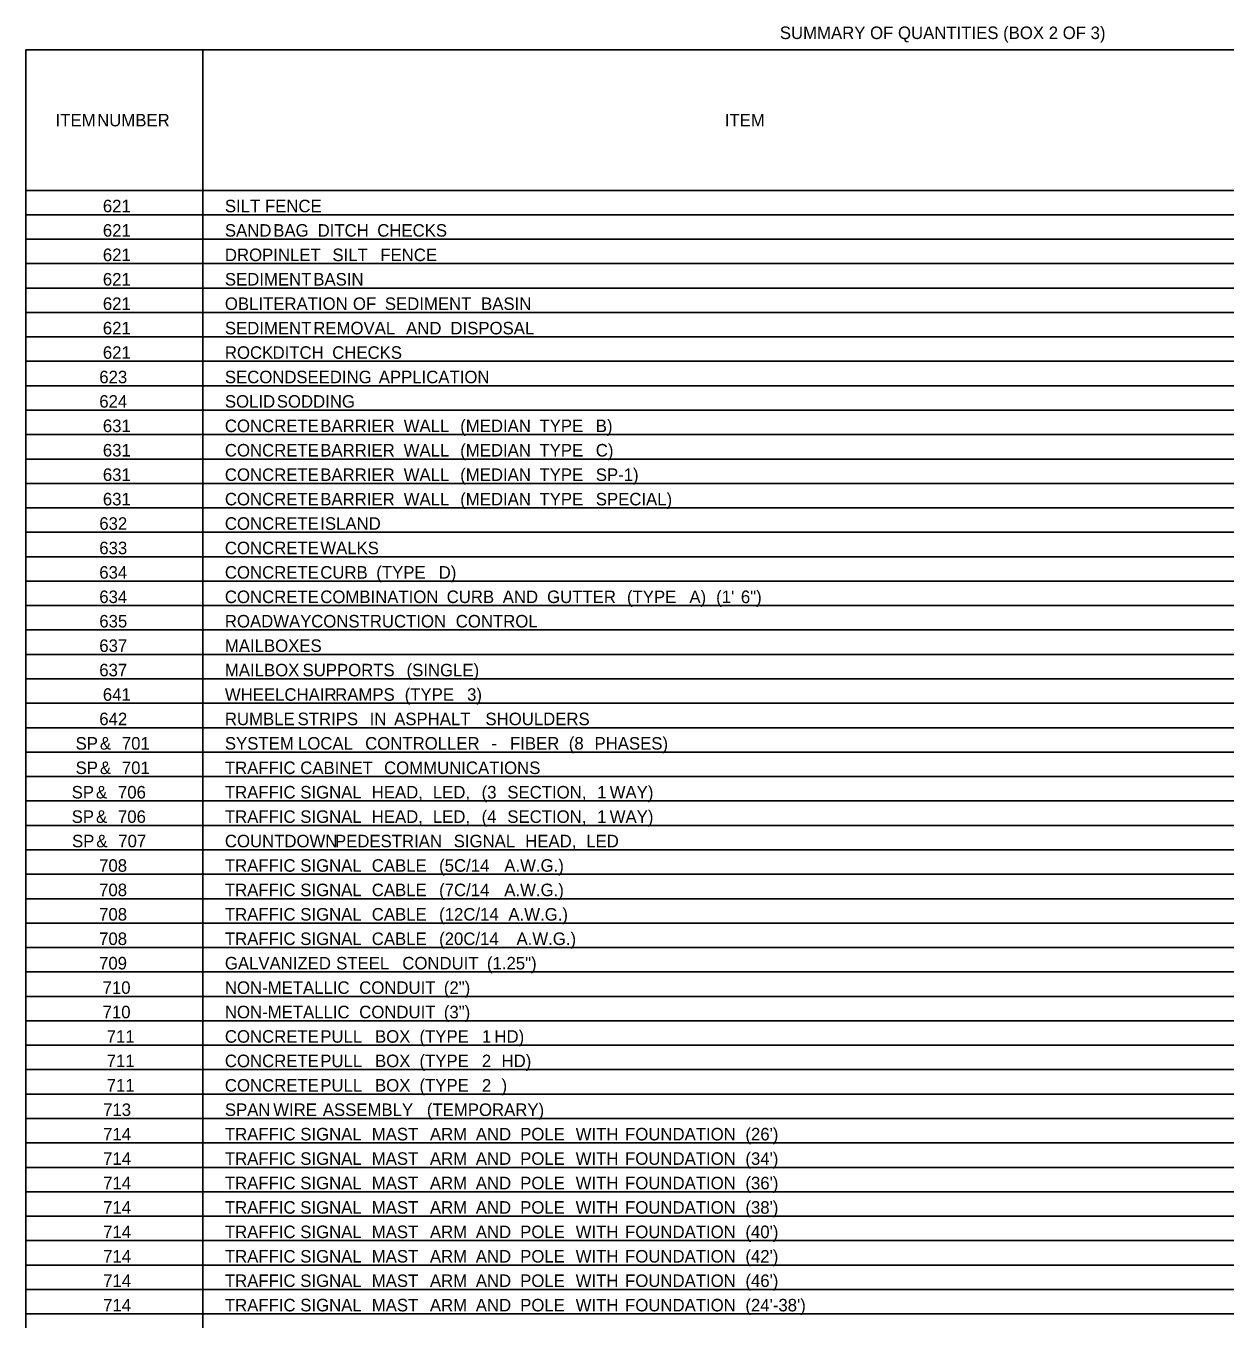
# Model space of a CAD drawing. Extents: x 1226603 to 1228117, y 151305 to 152343.
# Drawn here: x 1227295.3 to 1227702.3, y 151801.3 to 152240.1 of the extents above; entities that cross this region are included whole.
import ezdxf

# ---------------------------------------------------------------- set-up
doc = ezdxf.new("R2010")
doc.units = 0
doc.layers.add('R_Dimension', color=7, linetype='Continuous')

msp = doc.modelspace()

# ---------------------------------------------------------------- linework, layer by layer
at = {"layer": 'R_Dimension'}
for p, q in [((1227295.33, 152231.95), (1227925.18, 152231.95)), ((1227295.33, 151330.69), (1227295.33, 152231.95)), ((1227355.42, 151330.69), (1227355.42, 152231.95)), ((1227295.33, 152184.3), (1227925.18, 152184.3)), ((1227295.33, 152176.01), (1227925.18, 152176.01)), ((1227295.33, 152167.73), (1227925.18, 152167.73)), ((1227295.33, 152159.44), (1227925.18, 152159.44)), ((1227295.33, 152151.15), (1227925.18, 152151.15)), ((1227295.33, 152142.86), (1227925.18, 152142.86)), ((1227295.33, 152134.58), (1227925.18, 152134.58)), ((1227295.33, 152126.29), (1227925.18, 152126.29)), ((1227295.33, 152118), (1227925.18, 152118)), ((1227295.33, 152109.71), (1227925.18, 152109.71)), ((1227295.33, 152101.43), (1227925.18, 152101.43)), ((1227295.33, 152093.14), (1227925.18, 152093.14)), ((1227295.33, 152084.85), (1227925.18, 152084.85)), ((1227295.33, 152076.56), (1227925.18, 152076.56)), ((1227295.33, 152068.28), (1227925.18, 152068.28)), ((1227295.33, 152059.99), (1227925.18, 152059.99)), ((1227295.33, 152051.7), (1227925.18, 152051.7)), ((1227295.33, 152043.41), (1227925.18, 152043.41)), ((1227295.33, 152035.13), (1227925.18, 152035.13)), ((1227295.33, 152026.84), (1227925.18, 152026.84)), ((1227295.33, 152018.55), (1227925.18, 152018.55)), ((1227295.33, 152010.26), (1227925.18, 152010.26)), ((1227295.33, 152001.98), (1227925.18, 152001.98)), ((1227295.33, 151993.69), (1227925.18, 151993.69)), ((1227295.33, 151985.4), (1227925.18, 151985.4)), ((1227295.33, 151977.11), (1227925.18, 151977.11)), ((1227295.33, 151968.83), (1227925.18, 151968.83)), ((1227295.33, 151960.54), (1227925.18, 151960.54)), ((1227295.33, 151952.25), (1227925.18, 151952.25)), ((1227295.33, 151943.96), (1227925.18, 151943.96)), ((1227295.33, 151935.68), (1227925.18, 151935.68)), ((1227295.33, 151927.39), (1227925.18, 151927.39)), ((1227295.33, 151919.1), (1227925.18, 151919.1)), ((1227295.33, 151910.81), (1227925.18, 151910.81)), ((1227295.33, 151902.53), (1227925.18, 151902.53)), ((1227295.33, 151894.24), (1227925.18, 151894.24)), ((1227295.33, 151885.95), (1227925.18, 151885.95)), ((1227295.33, 151877.66), (1227925.18, 151877.66)), ((1227295.33, 151869.38), (1227925.18, 151869.38)), ((1227295.33, 151861.09), (1227925.18, 151861.09)), ((1227295.33, 151852.8), (1227925.18, 151852.8)), ((1227295.33, 151844.51), (1227925.18, 151844.51)), ((1227295.33, 151836.23), (1227925.18, 151836.23)), ((1227295.33, 151827.94), (1227925.18, 151827.94)), ((1227295.33, 151819.65), (1227925.18, 151819.65)), ((1227295.33, 151811.36), (1227925.18, 151811.36)), ((1227295.33, 151803.08), (1227925.18, 151803.08))]:
    msp.add_line(p, q, dxfattribs=at)

# ---------------------------------------------------------------- texts
for s, p in [('SUMMARY OF QUANTITIES (BOX 2 OF 3)', (1227551.19, 152235.63)), ('ITEM', (1227305.43, 152206)), (' NUMBER', (1227317.94, 152206)), ('ITEM', (1227532.52, 152206)), ('621', (1227321.46, 152176.86)), ('SILT', (1227362.87, 152176.86)), (' FENCE', (1227374.89, 152176.86)), ('621', (1227321.46, 152168.58)), ('SAND', (1227362.87, 152168.58)), (' BAG', (1227377.7, 152168.58)), (' DITCH', (1227392.76, 152168.58)), (' CHECKS', (1227413, 152168.58)), ('621', (1227321.46, 152160.29)), ('DROP', (1227362.87, 152160.29)), (' INLET', (1227377.7, 152160.29)), (' SILT', (1227397.78, 152160.29)), (' FENCE', (1227414.04, 152160.29)), ('621', (1227321.46, 152152)), ('SEDIMENT', (1227362.87, 152152)), (' BASIN', (1227391.29, 152152)), ('621', (1227321.46, 152143.71)), ('OBLITERATION', (1227362.87, 152143.71)), (' OF', (1227404.74, 152143.71)), (' SEDIMENT', (1227415.58, 152143.71)), (' BASIN', (1227448.24, 152143.71)), ('621', (1227321.46, 152135.43)), ('SEDIMENT', (1227362.87, 152135.43)), (' REMOVAL', (1227391.29, 152135.43)), (' AND', (1227422.78, 152135.43)), (' DISPOSAL', (1227437.84, 152135.43)), ('621', (1227321.46, 152127.14)), ('ROCK', (1227362.87, 152127.14)), (' DITCH', (1227377.47, 152127.14)), (' CHECKS', (1227397.71, 152127.14)), ('623', (1227320.25, 152118.85)), ('SECOND', (1227362.87, 152118.85)), (' SEEDING', (1227385.53, 152118.85)), (' APPLICATION', (1227413.51, 152118.85)), ('624', (1227320.25, 152110.56)), ('SOLID', (1227362.87, 152110.56)), (' SODDING', (1227378.9, 152110.56)), ('631', (1227321.46, 152102.28)), ('CONCRETE', (1227362.87, 152102.28)), (' BARRIER', (1227393.66, 152102.28)), (' WALL', (1227421.97, 152102.28)), (' (MEDIAN', (1227441.15, 152102.28)), (' TYPE', (1227468.05, 152102.28)), (' B)', (1227487.16, 152102.28)), ('631', (1227321.46, 152093.99)), ('CONCRETE', (1227362.87, 152093.99)), (' BARRIER', (1227393.66, 152093.99)), (' WALL', (1227421.97, 152093.99)), (' (MEDIAN', (1227441.15, 152093.99)), (' TYPE', (1227468.05, 152093.99)), (' C)', (1227487.16, 152093.99)), ('631', (1227321.46, 152085.7)), ('CONCRETE', (1227362.87, 152085.7)), (' BARRIER', (1227393.66, 152085.7)), (' WALL', (1227421.97, 152085.7)), (' (MEDIAN', (1227441.15, 152085.7)), (' TYPE', (1227468.05, 152085.7)), (' SP-1)', (1227487.16, 152085.7)), (' (MEDIAN', (1227441.15, 152077.41)), (' SPECIAL)', (1227487.16, 152077.41)), ('631', (1227321.46, 152077.41)), ('CONCRETE', (1227362.87, 152077.41)), (' BARRIER', (1227393.66, 152077.41)), (' WALL', (1227421.97, 152077.41)), (' TYPE', (1227468.05, 152077.41)), ('632', (1227320.25, 152069.13)), ('CONCRETE', (1227362.87, 152069.13)), (' ISLAND', (1227393.66, 152069.13)), ('633', (1227320.25, 152060.84)), ('CONCRETE', (1227362.87, 152060.84)), (' WALKS', (1227393.66, 152060.84)), ('634', (1227320.25, 152052.55)), ('CONCRETE', (1227362.87, 152052.55)), (' CURB', (1227393.66, 152052.55)), (' (TYPE', (1227412.67, 152052.55)), (' D)', (1227433.85, 152052.55)), ('634', (1227320.25, 152044.26)), ('CONCRETE', (1227362.87, 152044.26)), (' COMBINATION', (1227393.66, 152044.26)), (' CURB', (1227436.56, 152044.26)), (' AND', (1227455.57, 152044.26)), (' GUTTER', (1227470.63, 152044.26)), (' (TYPE', (1227497.74, 152044.26)), (' A)', (1227518.92, 152044.26)), (" (1'", (1227527.99, 152044.26)), (' 6")', (1227536.39, 152044.26)), ('635', (1227320.25, 152035.98)), ('ROADWAY', (1227362.87, 152035.98)), (' CONSTRUCTION', (1227390.58, 152035.98)), (' CONTROL', (1227439.64, 152035.98)), ('637', (1227320.25, 152027.69)), ('MAILBOXES', (1227362.87, 152027.69)), ('637', (1227320.25, 152019.4)), ('MAILBOX', (1227362.87, 152019.4)), (' SUPPORTS', (1227387.64, 152019.4)), (' (SINGLE)', (1227422.94, 152019.4)), ('641', (1227321.46, 152011.11)), ('WHEELCHAIR', (1227362.87, 152011.11)), (' RAMPS', (1227398.72, 152011.11)), (' (TYPE', (1227422.31, 152011.11)), (' 3)', (1227443.49, 152011.11)), ('642', (1227320.25, 152002.83)), ('RUMBLE', (1227362.87, 152002.83)), (' STRIPS', (1227385.97, 152002.83)), (' IN', (1227410.43, 152002.83)), (' ASPHALT', (1227418.73, 152002.83)), (' SHOULDERS', (1227449.72, 152002.83)), ('SP', (1227312.21, 151994.54)), (' &', (1227318.87, 151994.54)), (' 701', (1227326.33, 151994.54)), ('SYSTEM', (1227362.87, 151994.54)), (' LOCAL', (1227386.1, 151994.54)), (' CONTROLLER', (1227408.89, 151994.54)), (' FIBER', (1227458.05, 151994.54)), (' (8', (1227477.99, 151994.54)), (' PHASES)', (1227486.73, 151994.54)), (' -', (1227451.72, 151994.54)), ('SP', (1227312.21, 151986.25)), (' &', (1227318.87, 151986.25)), (' 701', (1227326.33, 151986.25)), ('TRAFFIC', (1227362.87, 151986.25)), (' CABINET', (1227386.87, 151986.25)), (' COMMUNICATIONS', (1227415.31, 151986.25)), ('SP', (1227310.88, 151977.96)), (' &', (1227317.54, 151977.96)), (' 706', (1227325.01, 151977.96)), ('TRAFFIC', (1227362.87, 151977.96)), (' SIGNAL', (1227386.87, 151977.96)), (' HEAD,', (1227411.13, 151977.96)), (' LED,', (1227431.85, 151977.96)), (' (3', (1227448.41, 151977.96)), (' SECTION,', (1227457.14, 151977.96)), (' 1', (1227487.63, 151977.96)), (' WAY)', (1227491.88, 151977.96)), ('SP', (1227310.88, 151969.68)), (' &', (1227317.54, 151969.68)), (' 706', (1227325.01, 151969.68)), ('TRAFFIC', (1227362.87, 151969.68)), (' SIGNAL', (1227386.87, 151969.68)), (' HEAD,', (1227411.13, 151969.68)), (' LED,', (1227431.85, 151969.68)), (' (4', (1227448.41, 151969.68)), (' SECTION,', (1227457.14, 151969.68)), (' 1', (1227487.63, 151969.68)), (' WAY)', (1227491.88, 151969.68)), ('SP', (1227311, 151961.39)), (' &', (1227317.66, 151961.39)), (' 707', (1227325.12, 151961.39)), ('COUNTDOWN', (1227362.87, 151961.39)), (' PEDESTRIAN', (1227398.65, 151961.39)), (' SIGNAL', (1227438.94, 151961.39)), (' HEAD,', (1227463.2, 151961.39)), (' LED', (1227483.92, 151961.39)), ('708', (1227320.19, 151953.1)), ('TRAFFIC', (1227362.87, 151953.1)), (' SIGNAL', (1227386.87, 151953.1)), (' CABLE', (1227411.13, 151953.1)), (' (5C/14', (1227433.99, 151953.1)), (' A.W.G.)', (1227456.11, 151953.1)), ('708', (1227320.19, 151944.81)), ('TRAFFIC', (1227362.87, 151944.81)), (' SIGNAL', (1227386.87, 151944.81)), (' CABLE', (1227411.13, 151944.81)), (' (7C/14', (1227433.99, 151944.81)), (' A.W.G.)', (1227456.11, 151944.81)), ('708', (1227320.19, 151936.53)), ('TRAFFIC', (1227362.87, 151936.53)), (' SIGNAL', (1227386.87, 151936.53)), (' CABLE', (1227411.13, 151936.53)), (' (12C/14', (1227433.99, 151936.53)), (' A.W.G.)', (1227457.51, 151936.53)), (' (20C/14', (1227433.99, 151928.24)), (' A.W.G.)', (1227460.26, 151928.24)), ('708', (1227320.19, 151928.24)), ('TRAFFIC', (1227362.87, 151928.24)), (' SIGNAL', (1227386.87, 151928.24)), (' CABLE', (1227411.13, 151928.24)), ('709', (1227320.17, 151919.95)), ('GALVANIZED', (1227362.87, 151919.95)), (' STEEL', (1227399.05, 151919.95)), (' CONDUIT', (1227421.5, 151919.95)), (' (1.25")', (1227450.22, 151919.95)), ('710', (1227321.38, 151911.66)), ('NON-METALLIC', (1227362.87, 151911.66)), (' CONDUIT', (1227406.88, 151911.66)), (' (2")', (1227435.59, 151911.66)), ('710', (1227321.38, 151903.38)), ('NON-METALLIC', (1227362.87, 151903.38)), (' CONDUIT', (1227406.88, 151903.38)), (' (3")', (1227435.59, 151903.38)), ('711', (1227322.76, 151895.09)), ('CONCRETE', (1227362.87, 151895.09)), (' PULL', (1227393.66, 151895.09)), (' BOX', (1227412.24, 151895.09)), (' (TYPE', (1227427.33, 151895.09)), (' 1', (1227448.51, 151895.09)), (' HD)', (1227452.76, 151895.09)), ('711', (1227322.76, 151886.8)), ('CONCRETE', (1227362.87, 151886.8)), (' PULL', (1227393.66, 151886.8)), (' BOX', (1227412.24, 151886.8)), (' (TYPE', (1227427.33, 151886.8)), (' 2', (1227448.51, 151886.8)), (' HD)', (1227455.17, 151886.8)), ('711', (1227322.76, 151878.51)), ('CONCRETE', (1227362.87, 151878.51)), (' PULL', (1227393.66, 151878.51)), (' BOX', (1227412.24, 151878.51)), (' (TYPE', (1227427.33, 151878.51)), (' 2', (1227448.51, 151878.51)), (' )', (1227455.17, 151878.51)), ('713', (1227321.56, 151870.23)), ('SPAN', (1227362.87, 151870.23)), (' WIRE', (1227377.7, 151870.23)), (' ASSEMBLY', (1227394.53, 151870.23)), (' (TEMPORARY)', (1227429.84, 151870.23)), ('714', (1227321.56, 151861.94)), ('TRAFFIC', (1227362.87, 151861.94)), (' SIGNAL', (1227386.87, 151861.94)), (' MAST', (1227411.13, 151861.94)), (' ARM', (1227430.87, 151861.94)), (' AND', (1227446.44, 151861.94)), (' POLE', (1227461.5, 151861.94)), (' WITH', (1227480.34, 151861.94)), (' FOUNDATION', (1227497.1, 151861.94)), (" (26')", (1227537.93, 151861.94)), (" (34')", (1227537.93, 151853.65)), ('714', (1227321.56, 151853.65)), ('TRAFFIC', (1227362.87, 151853.65)), (' SIGNAL', (1227386.87, 151853.65)), (' MAST', (1227411.13, 151853.65)), (' ARM', (1227430.87, 151853.65)), (' AND', (1227446.44, 151853.65)), (' POLE', (1227461.5, 151853.65)), (' WITH', (1227480.34, 151853.65)), (' FOUNDATION', (1227497.1, 151853.65)), ('714', (1227321.56, 151845.36)), ('TRAFFIC', (1227362.87, 151845.36)), (' SIGNAL', (1227386.87, 151845.36)), (' MAST', (1227411.13, 151845.36)), (' ARM', (1227430.87, 151845.36)), (' AND', (1227446.44, 151845.36)), (' POLE', (1227461.5, 151845.36)), (' WITH', (1227480.34, 151845.36)), (' FOUNDATION', (1227497.1, 151845.36)), (" (36')", (1227537.93, 151845.36)), ('714', (1227321.56, 151837.08)), ('TRAFFIC', (1227362.87, 151837.08)), (' SIGNAL', (1227386.87, 151837.08)), (' MAST', (1227411.13, 151837.08)), (' ARM', (1227430.87, 151837.08)), (' AND', (1227446.44, 151837.08)), (' POLE', (1227461.5, 151837.08)), (' WITH', (1227480.34, 151837.08)), (' FOUNDATION', (1227497.1, 151837.08)), (" (38')", (1227537.93, 151837.08)), ('714', (1227321.56, 151828.79)), ('TRAFFIC', (1227362.87, 151828.79)), (' SIGNAL', (1227386.87, 151828.79)), (' MAST', (1227411.13, 151828.79)), (' ARM', (1227430.87, 151828.79)), (' AND', (1227446.44, 151828.79)), (' POLE', (1227461.5, 151828.79)), (' WITH', (1227480.34, 151828.79)), (' FOUNDATION', (1227497.1, 151828.79)), (" (40')", (1227537.93, 151828.79)), ('714', (1227321.56, 151820.5)), ('TRAFFIC', (1227362.87, 151820.5)), (' SIGNAL', (1227386.87, 151820.5)), (' MAST', (1227411.13, 151820.5)), (' ARM', (1227430.87, 151820.5)), (' AND', (1227446.44, 151820.5)), (' POLE', (1227461.5, 151820.5)), (' WITH', (1227480.34, 151820.5)), (' FOUNDATION', (1227497.1, 151820.5)), (" (42')", (1227537.93, 151820.5)), ('714', (1227321.56, 151812.21)), ('TRAFFIC', (1227362.87, 151812.21)), (' SIGNAL', (1227386.87, 151812.21)), (' MAST', (1227411.13, 151812.21)), (' ARM', (1227430.87, 151812.21)), (' AND', (1227446.44, 151812.21)), (' POLE', (1227461.5, 151812.21)), (' WITH', (1227480.34, 151812.21)), (' FOUNDATION', (1227497.1, 151812.21)), (" (46')", (1227537.93, 151812.21)), ('714', (1227321.56, 151803.93)), ('TRAFFIC', (1227362.87, 151803.93)), (' SIGNAL', (1227386.87, 151803.93)), (' MAST', (1227411.13, 151803.93)), (' ARM', (1227430.87, 151803.93)), (' AND', (1227446.44, 151803.93)), (' POLE', (1227461.5, 151803.93)), (' WITH', (1227480.34, 151803.93)), (' FOUNDATION', (1227497.1, 151803.93)), (" (24'-38')", (1227537.93, 151803.93))]:
    msp.add_text(s, height=4.25, dxfattribs=at).set_placement(p)

doc.saveas('drawing.dxf')
